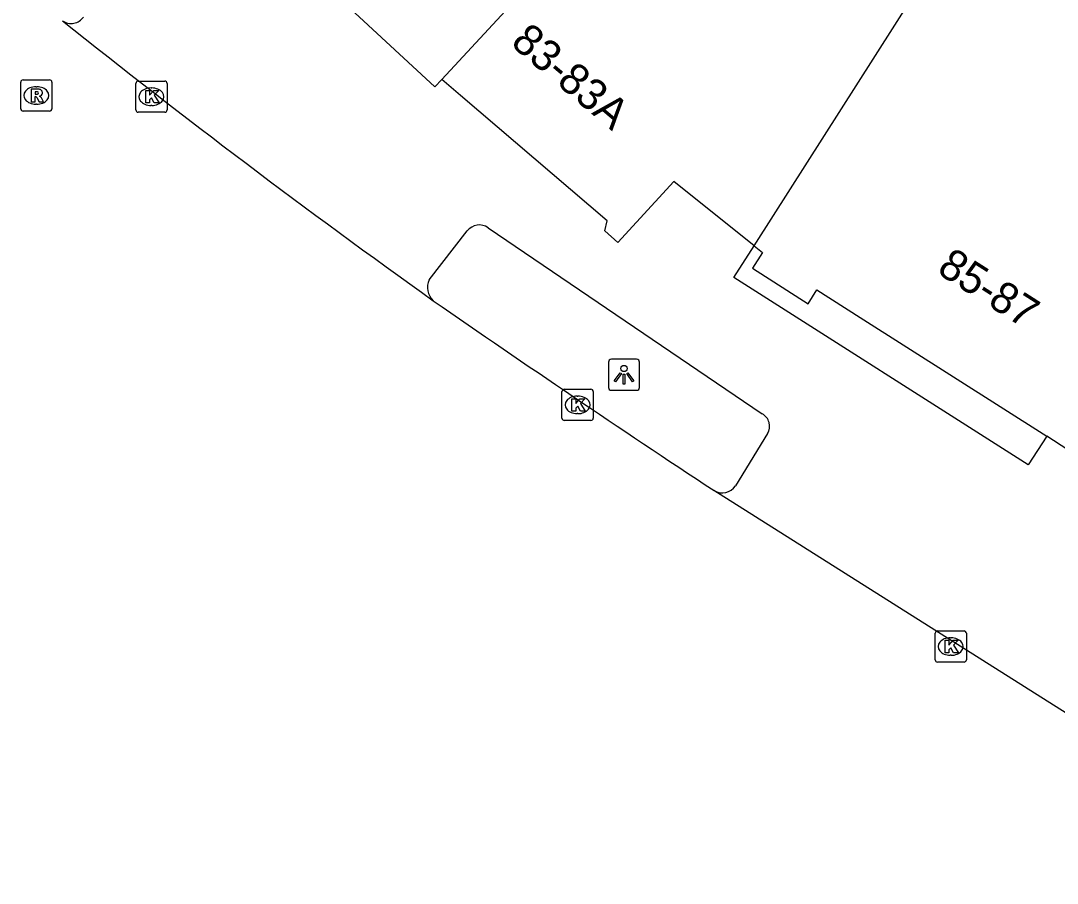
# Model space of a CAD drawing. Extents: x 161771 to 163125, y 382479 to 383177.
# Drawn here: x 162085.73 to 162118.96, y 382677.16 to 382704.81 of the extents above; entities that cross this region are included whole.
import ezdxf

# ---------------------------------------------------------------- set-up
doc = ezdxf.new("R2010")
doc.units = 0
for name, color, linetype in [('IMGEO_Kolk', 7, 'Continuous'), ('IMGEO_Lichtpunt', 7, 'Continuous'), ('IMGEO_Pand', 7, 'Continuous'), ('IMGEO_Pand_nummerreeks', 7, 'Continuous'), ('IMGEO_Rijbaan_lokaal_open', 7, 'Continuous'), ('IMGEO_Rioolput', 7, 'Continuous'), ('IMGEO_Voetpad_open', 7, 'Continuous')]:
    doc.layers.add(name, color=color, linetype=linetype)

msp = doc.modelspace()

# ---------------------------------------------------------------- linework, layer by layer
at = {"layer": 'IMGEO_Kolk'}
for p, q in [((162089.416, 382701.952), (162089.416, 382702.804)), ((162089.491, 382702.878), (162090.343, 382702.878)), ((162090.417, 382702.804), (162090.417, 382701.952)), ((162089.904, 382702.658), (162089.929, 382702.658)), ((162090.343, 382701.878), (162089.491, 382701.878)), ((162089.927, 382702.098), (162089.902, 382702.098)), ((162103.082, 382692.069), (162103.082, 382692.921)), ((162103.157, 382692.995), (162104.009, 382692.995)), ((162104.083, 382692.921), (162104.083, 382692.069)), ((162103.57, 382692.775), (162103.595, 382692.775)), ((162103.593, 382692.215), (162103.568, 382692.215)), ((162104.009, 382691.995), (162103.157, 382691.995)), ((162115.048, 382684.32), (162115.048, 382685.172)), ((162115.123, 382685.246), (162115.975, 382685.246)), ((162116.049, 382685.172), (162116.049, 382684.32)), ((162115.536, 382685.026), (162115.561, 382685.026)), ((162115.975, 382684.246), (162115.123, 382684.246)), ((162115.559, 382684.466), (162115.534, 382684.466))]:
    msp.add_line(p, q, dxfattribs=at)
for points in [[(162089.416, 382701.952), (162089.416, 382702.804)], [(162089.491, 382702.878), (162090.343, 382702.878)], [(162090.417, 382702.804), (162090.417, 382701.952)], [(162089.737, 382702.578), (162089.86, 382702.578), (162089.86, 382702.427), (162089.99, 382702.578), (162090.154, 382702.578), (162090.008, 382702.427), (162090.161, 382702.178), (162090.009, 382702.178), (162089.924, 382702.342), (162089.86, 382702.275), (162089.86, 382702.178), (162089.737, 382702.178), (162089.737, 382702.578)], [(162090.343, 382701.878), (162089.491, 382701.878)], [(162103.082, 382692.069), (162103.082, 382692.921)], [(162103.157, 382692.995), (162104.009, 382692.995)], [(162104.083, 382692.921), (162104.083, 382692.069)], [(162103.403, 382692.695), (162103.526, 382692.695), (162103.526, 382692.544), (162103.656, 382692.695), (162103.82, 382692.695), (162103.674, 382692.544), (162103.827, 382692.295), (162103.675, 382692.295), (162103.59, 382692.459), (162103.526, 382692.392), (162103.526, 382692.295), (162103.403, 382692.295), (162103.403, 382692.695)], [(162104.009, 382691.995), (162103.157, 382691.995)], [(162115.048, 382684.32), (162115.048, 382685.172)], [(162115.123, 382685.246), (162115.975, 382685.246)], [(162116.049, 382685.172), (162116.049, 382684.32)], [(162115.369, 382684.946), (162115.492, 382684.946), (162115.492, 382684.795), (162115.622, 382684.946), (162115.786, 382684.946), (162115.64, 382684.795), (162115.793, 382684.546), (162115.641, 382684.546), (162115.556, 382684.71), (162115.492, 382684.643), (162115.492, 382684.546), (162115.369, 382684.546), (162115.369, 382684.946)], [(162115.975, 382684.246), (162115.123, 382684.246)]]:
    msp.add_lwpolyline(points, dxfattribs=at)
for centre, start, end in [((162089.493, 382702.802), 91.552, 178.448), ((162089.493, 382702.802), 91.552, 178.448), ((162090.341, 382702.802), 1.552, 88.448), ((162090.341, 382702.802), 1.552, 88.448), ((162089.493, 382701.954), 181.552, 268.448), ((162089.493, 382701.954), 181.552, 268.448), ((162090.341, 382701.954), 271.552, 358.448), ((162090.341, 382701.954), 271.552, 358.448), ((162103.159, 382692.919), 91.552, 178.448), ((162103.159, 382692.919), 91.552, 178.448), ((162104.007, 382692.919), 1.552, 88.448), ((162104.007, 382692.919), 1.552, 88.448), ((162103.159, 382692.071), 181.552, 268.448), ((162103.159, 382692.071), 181.552, 268.448), ((162104.007, 382692.071), 271.552, 358.448), ((162104.007, 382692.071), 271.552, 358.448), ((162115.125, 382685.17), 91.552, 178.448), ((162115.125, 382685.17), 91.552, 178.448), ((162115.973, 382685.17), 1.552, 88.448), ((162115.973, 382685.17), 1.552, 88.448), ((162115.125, 382684.322), 181.552, 268.448), ((162115.125, 382684.322), 181.552, 268.448), ((162115.973, 382684.322), 271.552, 358.448), ((162115.973, 382684.322), 271.552, 358.448)]:
    msp.add_arc(centre, 0.0765, start, end, dxfattribs=at)
for centre, major_axis, ratio, start_param, end_param in [((162089.903, 382702.378), (-0.387, 0.002), 0.722429, 4.712389, 7.853982), ((162089.928, 382702.378), (-0.39, 0.002), 0.717154, 1.570796, 4.712389), ((162103.569, 382692.495), (-0.387, 0.002), 0.722429, 4.712389, 7.853982), ((162103.594, 382692.495), (-0.39, 0.002), 0.717154, 1.570796, 4.712389), ((162115.535, 382684.746), (-0.387, 0.002), 0.722429, 4.712389, 7.853982), ((162115.56, 382684.746), (-0.39, 0.002), 0.717154, 1.570796, 4.712389)]:
    msp.add_ellipse(centre, major_axis=major_axis, ratio=ratio, start_param=start_param, end_param=end_param, dxfattribs=at)
at = {"layer": 'IMGEO_Lichtpunt'}
for p, q in [((162104.573, 382693.864), (162104.573, 382693.057)), ((162104.573, 382693.864), (162104.573, 382693.057)), ((162105.475, 382693.959), (162104.667, 382693.959)), ((162105.475, 382693.959), (162104.667, 382693.959)), ((162105.569, 382693.057), (162105.569, 382693.864)), ((162105.569, 382693.057), (162105.569, 382693.864)), ((162104.667, 382692.963), (162105.475, 382692.963)), ((162104.667, 382692.963), (162105.475, 382692.963))]:
    msp.add_line(p, q, dxfattribs=at)
for points in [[(162104.947, 382693.528), (162104.986, 382693.5), (162104.798, 382693.238), (162104.76, 382693.265), (162104.947, 382693.528)], [(162105.049, 382693.48), (162105.096, 382693.48), (162105.096, 382693.158), (162105.049, 382693.158), (162105.049, 382693.48)], [(162105.159, 382693.5), (162105.197, 382693.527), (162105.384, 382693.265), (162105.345, 382693.237), (162105.159, 382693.5)]]:
    msp.add_lwpolyline(points, dxfattribs=at)
msp.add_circle((162105.072, 382693.662), 0.0994, dxfattribs=at)
for centre, start, end in [((162104.667, 382693.864), 90, 180), ((162104.667, 382693.864), 90, 180), ((162105.475, 382693.864), 0, 90), ((162105.475, 382693.864), 0, 90), ((162104.667, 382693.057), 180, 270), ((162104.667, 382693.057), 180, 270), ((162105.475, 382693.057), 270, 0), ((162105.475, 382693.057), 270, 360)]:
    msp.add_arc(centre, 0.0946, start, end, dxfattribs=at)
at = {"layer": 'IMGEO_Pand'}
for points in [[(162132.852, 382740.143), (162123.57, 382730.005), (162108.878, 382713.348), (162099.225, 382702.933)], [(162109.246, 382697.596), (162117.027, 382709.813), (162119.138, 382712.068), (162139.628, 382733.955)], [(162099.225, 382702.933), (162099.002, 382702.692), (162090.877, 382710.223), (162090.512, 382710.562)], [(162109.246, 382697.596), (162106.669, 382699.658), (162104.869, 382697.7), (162104.458, 382698.078), (162104.528, 382698.394), (162099.827, 382702.418), (162099.225, 382702.933)], [(162109.246, 382697.596), (162109.51, 382697.385), (162109.188, 382696.879), (162110.977, 382695.741), (162111.257, 382696.181), (162112.64, 382695.3), (162118.626, 382691.489)], [(162119.304, 382691.057), (162118.626, 382691.489)]]:
    msp.add_lwpolyline(points, dxfattribs=at)
at = {"layer": 'IMGEO_Rijbaan_lokaal_open'}
msp.add_lwpolyline([(162127.873, 382677.156), (162107.957, 382689.747)], dxfattribs=at)
for centre, radius, start, end in [((162260.432, 382922.073), 277.952, 231.41133, 234.48276), ((162363.849, 383077.651), 464.704, 235.24807, 236.58803)]:
    msp.add_arc(centre, radius, start, end, dxfattribs=at)
at = {"layer": 'IMGEO_Rioolput'}
for p, q in [((162085.725, 382701.992), (162085.725, 382702.844)), ((162085.8, 382702.918), (162086.652, 382702.918)), ((162086.726, 382702.844), (162086.726, 382701.992)), ((162086.213, 382702.698), (162086.238, 382702.698)), ((162086.236, 382702.138), (162086.211, 382702.138)), ((162086.652, 382701.918), (162085.8, 382701.918))]:
    msp.add_line(p, q, dxfattribs=at)
for points in [[(162085.725, 382701.992), (162085.725, 382702.844)], [(162085.8, 382702.918), (162086.652, 382702.918)], [(162086.726, 382702.844), (162086.726, 382701.992)], [(162086.314, 382702.616), (162086.062, 382702.618), (162086.062, 382702.218)], [(162086.24, 382702.537), (162086.186, 382702.537), (162086.186, 382702.456)], [(162086.186, 382702.456), (162086.238, 382702.456)], [(162086.062, 382702.218), (162086.186, 382702.218), (162086.186, 382702.38), (162086.197, 382702.38)], [(162086.244, 382702.351), (162086.315, 382702.218), (162086.455, 382702.218), (162086.39, 382702.344)], [(162086.652, 382701.918), (162085.8, 382701.918)]]:
    msp.add_lwpolyline(points, dxfattribs=at)
for centre, radius, start, end in [((162085.802, 382702.842), 0.0765, 91.552, 178.448), ((162085.802, 382702.842), 0.0765, 91.552, 178.448), ((162086.65, 382702.842), 0.0765, 1.552, 88.448), ((162086.65, 382702.842), 0.0765, 1.552, 88.448), ((162086.222, 382702.645), 0.19, 274.7715, 282.9687), ((162086.246, 382702.441), 0.0964, 77.0061, 93.1865), ((162086.26, 382702.498), 0.0378, 276.6634, 79.6772), ((162086.313, 382702.506), 0.109, 350.3612, 89.416), ((162086.311, 382702.506), 0.112, 277.5842, 350.9817), ((162086.196, 382702.327), 0.0533, 26.0293, 88.6989), ((162086.295, 382702.291), 0.108, 29.5134, 73.7905), ((162085.802, 382701.994), 0.0765, 181.552, 268.448), ((162085.802, 382701.994), 0.0765, 181.552, 268.448), ((162086.65, 382701.994), 0.0765, 271.552, 358.448), ((162086.65, 382701.994), 0.0765, 271.552, 358.448)]:
    msp.add_arc(centre, radius, start, end, dxfattribs=at)
for centre, major_axis, ratio, start_param, end_param in [((162086.212, 382702.418), (-0.387, 0.002), 0.722429, 4.712389, 7.853982), ((162086.237, 382702.418), (-0.39, 0.002), 0.717154, 1.570796, 4.712389)]:
    msp.add_ellipse(centre, major_axis=major_axis, ratio=ratio, start_param=start_param, end_param=end_param, dxfattribs=at)
at = {"layer": 'IMGEO_Voetpad_open'}
for points in [[(162100.714, 382698.174), (162109.503, 382692.211)], [(162098.82, 382696.511), (162100.045, 382698.073)], [(162118.626, 382691.489), (162118.03, 382690.57), (162108.592, 382696.578), (162109.246, 382697.596)], [(162109.672, 382691.573), (162108.651, 382689.904)]]:
    msp.add_lwpolyline(points, dxfattribs=at)
for centre, radius, start, end in [((162087.345, 382705.204), 0.479, 234.3777, 325.6189), ((162100.431, 382697.784), 0.482, 54.0159, 143.1545), ((162099.344, 382696.266), 0.578, 154.9251, 227.8909), ((162109.278, 382691.81), 0.46, 328.9722, 60.7005), ((162108.222, 382690.189), 0.515, 239.0453, 326.449)]:
    msp.add_arc(centre, radius, start, end, dxfattribs=at)

# ---------------------------------------------------------------- texts
at = {"layer": 'IMGEO_Pand_nummerreeks'}
for s, rotation, p in [('83-83A', 319.7726, (162101.401, 382704.049)), ('85-87', 327.5133, (162115.068, 382696.742))]:
    msp.add_text(s, height=1, rotation=rotation, dxfattribs=at).set_placement(p)

doc.saveas('drawing.dxf')
